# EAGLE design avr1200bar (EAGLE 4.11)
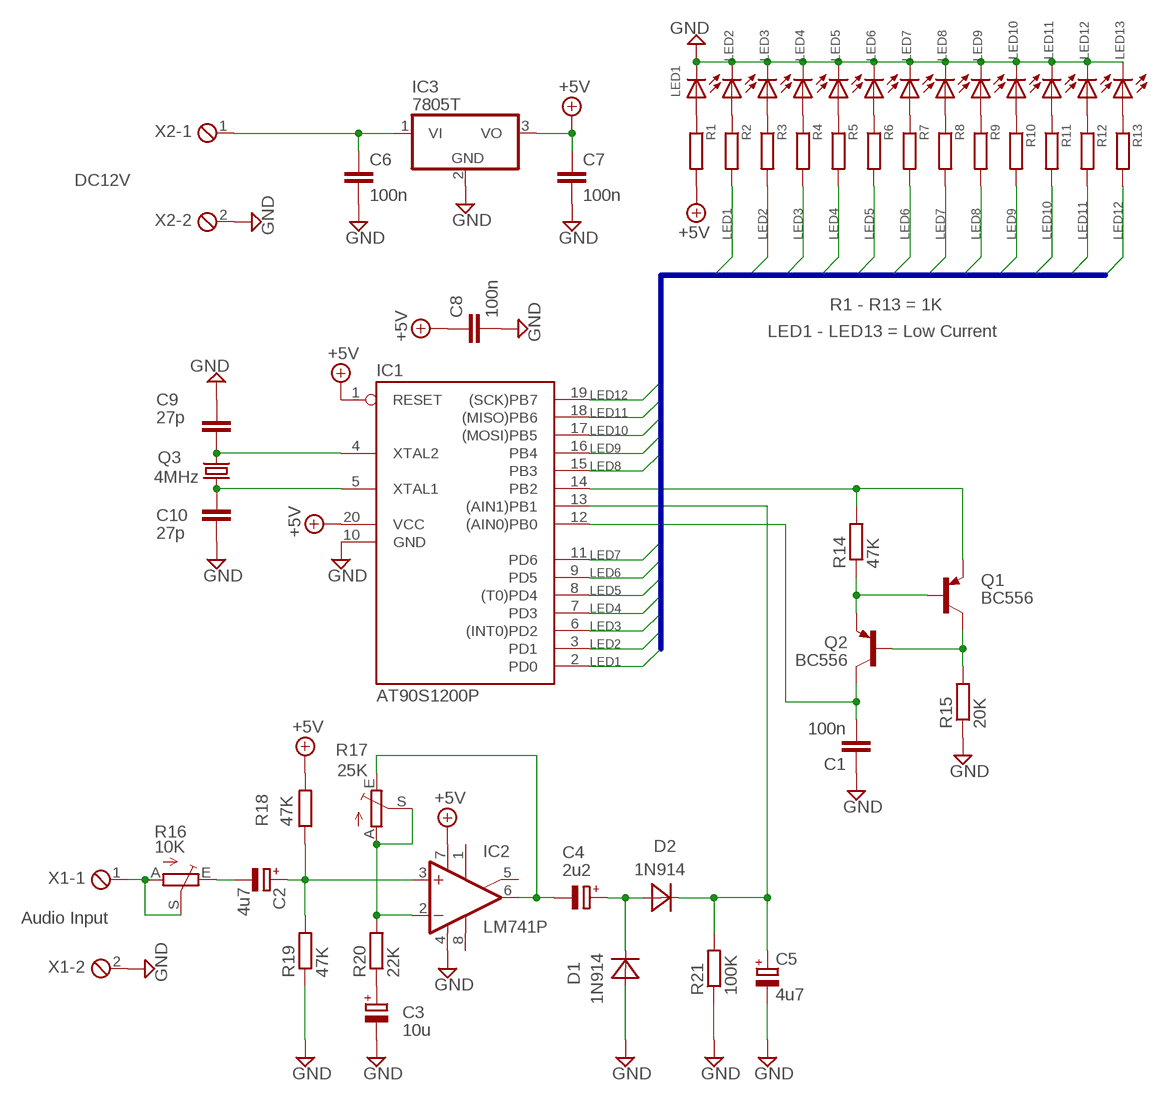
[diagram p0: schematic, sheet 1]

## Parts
C1  100n  C-EU050-025X075  [C050-025X075]
C2  4u7  CPOL-EUE2-5  [E2-5]
C3  10u  CPOL-EUE2-5  [E2-5]
C4  2u2  CPOL-EUE2-5  [E2-5]
C5  4u7  CPOL-EUE2-5  [E2-5]
C6  100n  C-EU050-025X075  [C050-025X075]
C7  100n  C-EU050-025X075  [C050-025X075]
C8  100n  C-EU050-025X075  [C050-025X075]
C9  27p  C-EU050-024X044  [C050-024X044]
C10  27p  C-EU050-024X044  [C050-024X044]
D1  1N914  DIODE-7,5  [D-7,5]
D2  1N914  DIODE-7,5  [D-7,5]
IC1  AT90S1200P  [DIL20]
IC2  LM741P  [DIL08]
IC3  7805T  7812T  [TO220H]
LED1  LEDSQR2X5  [LED2X5]
LED2  LEDSQR2X5  [LED2X5]
LED3  LEDSQR2X5  [LED2X5]
LED4  LEDSQR2X5  [LED2X5]
LED5  LEDSQR2X5  [LED2X5]
LED6  LEDSQR2X5  [LED2X5]
LED7  LEDSQR2X5  [LED2X5]
LED8  LEDSQR2X5  [LED2X5]
LED9  LEDSQR2X5  [LED2X5]
LED10  LEDSQR2X5  [LED2X5]
LED11  LEDSQR2X5  [LED2X5]
LED12  LEDSQR2X5  [LED2X5]
LED13  LEDSQR2X5  [LED2X5]
Q1  BC556  [TO92-EBC]
Q2  BC556  [TO92-EBC]
Q3  4MHz  CRYTALHC49S  [HC49/S]
R1  R-EU_0204/7  [0204/7]
R2  R-EU_0204/7  [0204/7]
R3  R-EU_0204/7  [0204/7]
R4  R-EU_0204/7  [0204/7]
R5  R-EU_0204/7  [0204/7]
R6  R-EU_0204/7  [0204/7]
R7  R-EU_0204/7  [0204/7]
R8  R-EU_0204/7  [0204/7]
R9  R-EU_0204/7  [0204/7]
R10  R-EU_0204/7  [0204/7]
R11  R-EU_0204/7  [0204/7]
R12  R-EU_0204/7  [0204/7]
R13  R-EU_0204/7  [0204/7]
R14  47K  R-EU_0204/7  [0204/7]
R15  20K  R-EU_0204/7  [0204/7]
R16  10K  TRIM_EU-CA9V  [CA9V]
R17  25K  TRIM_EU-CA9V  [CA9V]
R18  47K  R-EU_0204/7  [0204/7]
R19  47K  R-EU_0204/7  [0204/7]
R20  22K  R-EU_0204/7  [0204/7]
R21  100K  R-EU_0204/7  [0204/7]
X1  MPT2  [2POL254]
X2  MPT2  [2POL254]

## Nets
+5V: C7.1 C8.1 IC1.1(RESET) IC1.20(VCC) IC2.7(V+) IC3.3(VO) R1.2 R18.2
GND: C1.1 C3.- C5.- C6.2 C7.2 C8.2 C9.1 C10.2 D1.1(A) IC1.10(GND) IC2.4(V-) IC3.2(GND) LED1.K(C) LED2.K(C) LED3.K(C) LED4.K(C) LED5.K(C) LED6.K(C) LED7.K(C) LED8.K(C) LED9.K(C) LED10.K(C) LED11.K(C) LED12.K(C) LED13.K(C) R15.1 R19.1 R21.1 X1.2 X2.2
LED1: IC1.2(PD0) R2.2
LED2: IC1.3(PD1) R3.2
LED3: IC1.6((INT0)PD2) R4.2
LED4: IC1.7(PD3) R5.2
LED5: IC1.8((T0)PD4) R6.2
LED6: IC1.9(PD5) R7.2
LED7: IC1.11(PD6) R8.2
LED8: IC1.15(PB3) R9.2
LED9: IC1.16(PB4) R10.2
LED10: IC1.17((MOSI)PB5) R11.2
LED11: IC1.18((MISO)PB6) R12.2
LED12: IC1.19((SCK)PB7) R13.2
N$1: LED1.A R1.1
N$2: LED2.A R2.1
N$3: LED3.A R3.1
N$4: LED4.A R4.1
N$5: LED5.A R5.1
N$6: LED6.A R6.1
N$7: LED7.A R7.1
N$8: LED8.A R8.1
N$9: LED9.A R9.1
N$10: LED10.A R10.1
N$11: LED11.A R11.1
N$12: LED12.A R12.1
N$13: LED13.A R13.1
N$14: Q1.C Q2.B R15.2
N$15: C1.2 IC1.12((AIN0)PB0) Q2.C
N$16: Q1.B Q2.E R14.1
N$17: IC1.14(PB2) Q1.E R14.2
N$18: C3.+ R20.1
N$19: C2.- R16.E
N$20: C2.+ IC2.3(+IN) R18.1 R19.2
N$21: IC2.2(-IN) R17.A R17.S R20.2
N$22: C4.- IC2.6(OUT) R17.E
N$23: R16.A R16.S X1.1
N$24: C4.+ D1.2(K) D2.1(A)
N$25: C5.+ D2.2(K) IC1.13((AIN1)PB1) R21.2
N$27: C10.1 IC1.5(XTAL1) Q3.1
N$28: C9.2 IC1.4(XTAL2) Q3.2
N$29: C6.1 IC3.1(VI) X2.1
Unconnected: IC2.1(ON1) IC2.5(ON2) IC2.8(OPT)

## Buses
B$1

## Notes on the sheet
- DC12V
- R1 - R13 = 1K
- LED1 - LED13 = Low Current
- Audio Input

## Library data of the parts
C1 C6-C10 = rcl:C-EU: CAPACITOR, European symbol
C2-C5 = rcl:CPOL-EU: POLARIZED CAPACITOR, European symbol
D1 D2 = discrete:DIODE-7,5
IC1 = atmel:AT90S1200: MICROCONTROLLER 1 Kbytes FLASH 64 bytes EEPROM
IC2 = linear:*741: OP AMP
IC3 = linear:78*: Positive VOLTAGE REGULATOR
LED1-LED13 = led:LED: LED
Q1 Q2 = transistor-pnp:BC556*: PNP Transistror
Q3 = crystal:CRYTAL: CRYSTAL
R1-R15 R18-R21 = rcl:R-EU_: RESISTOR, European symbol
R16 R17 = pot:TRIM_EU-: POTENTIOMETER
X1 X2 = con-phoenix-254:MPT2: PHOENIX CONNECTOR

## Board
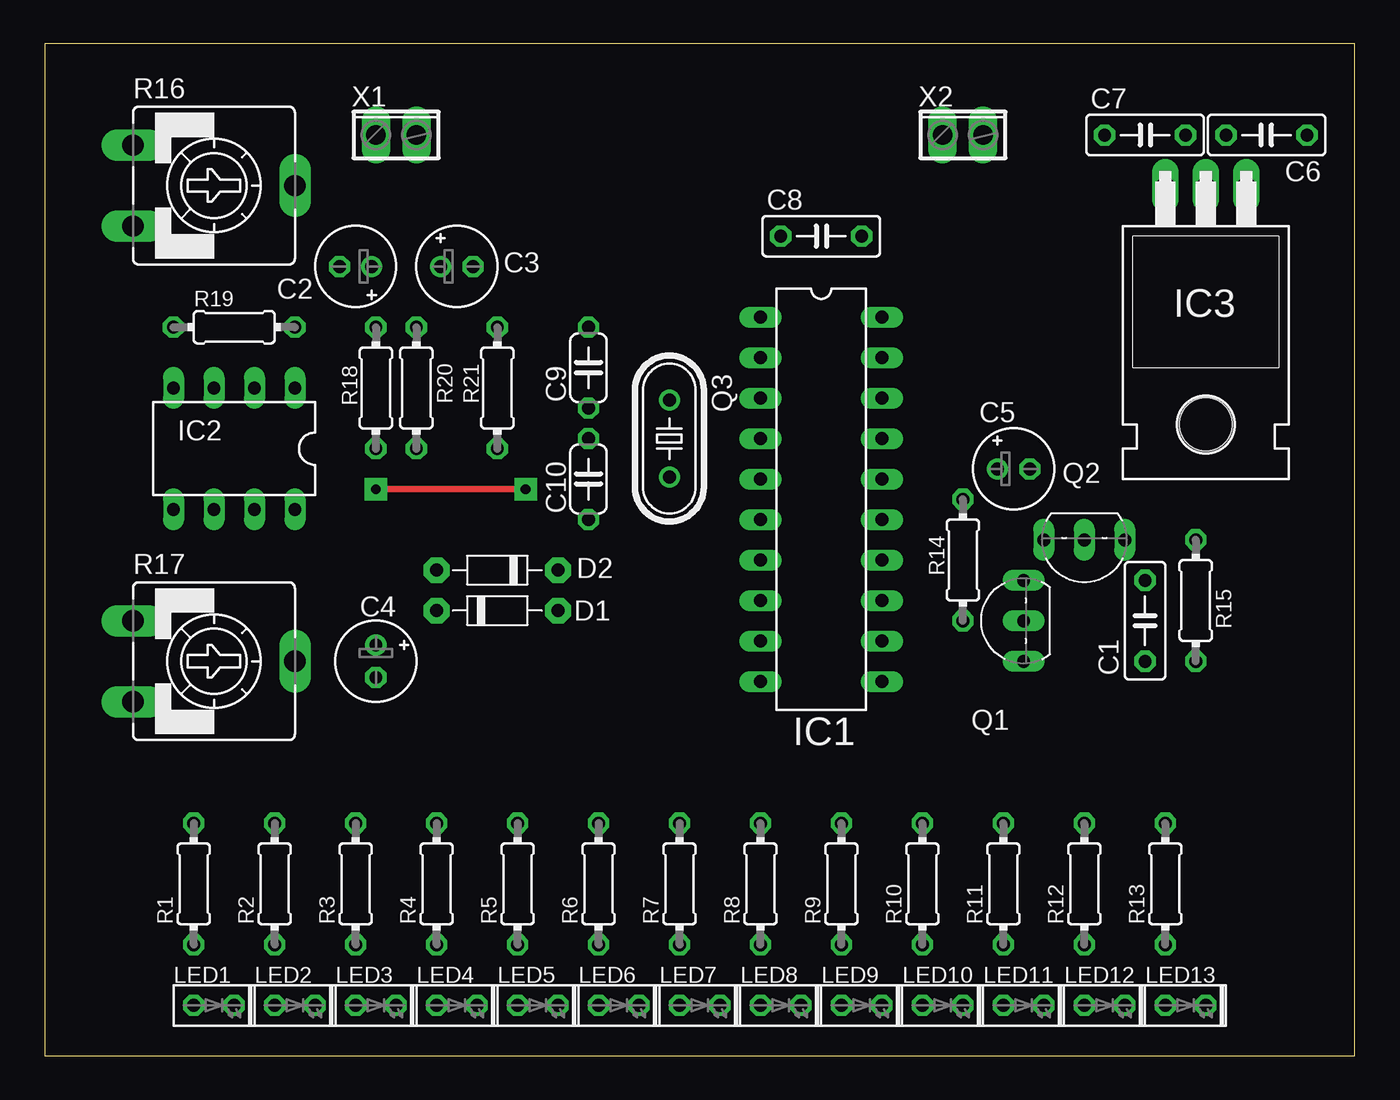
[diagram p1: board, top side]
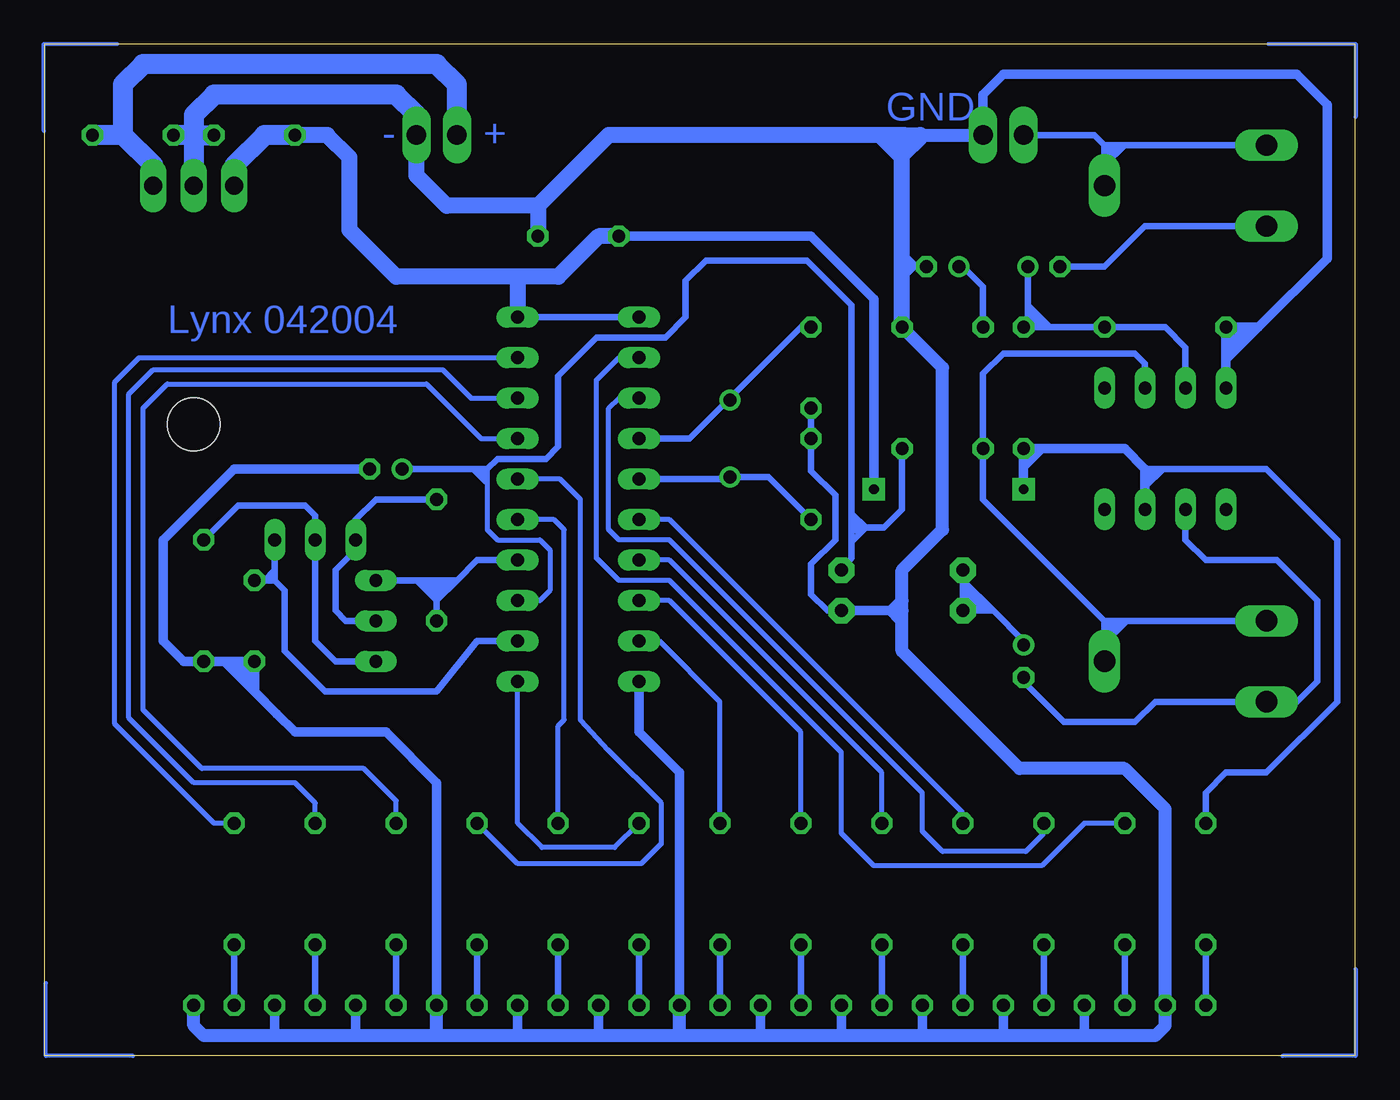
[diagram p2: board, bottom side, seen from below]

Size 82.22 x 63.49 mm. Coordinates in mm from the lower left corner, seen from the top.
Outline: 0,0 82.22,0 82.22,63.49 0,63.49 0,0
Copper layers (1*16): Top 0.035mm / dielectric 1.5mm / Bottom 0.035mm
Design rules "default": minimum track width 10mil, minimum drill 24mil, track to track 8mil, track to pad 8mil, pad to pad 8mil, via to via 8mil, smd to smd 8mil, copper to edge 40mil, drill to drill 8mil, minimum pad ring 10mil, minimum via ring 8mil, stop-mask expansion 4mil, vias tented up to drill 0mil, thermal gap 10mil

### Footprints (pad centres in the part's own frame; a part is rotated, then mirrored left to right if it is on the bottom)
C050-025X075 = drill 0.813 octagon: 1 -2.54,0; 2 2.54,0
E2-5 = drill 0.813 pad 1.27 round: + -1.016,0 | drill 0.813 pad 1.27 octagon: - 1.016,0
C050-024X044 = drill 0.813 octagon: 1 -2.54,0; 2 2.54,0
D-7,5 = drill 0.813 pad 1.6 octagon: 1 -3.81,0; 2 3.81,0
DIL20 = drill 0.813 long: 1 -11.43,-3.81; 2 -8.89,-3.81; 3 -6.35,-3.81; 4 -3.81,-3.81; 5 -1.27,-3.81; 6 1.27,-3.81; 7 3.81,-3.81; 8 6.35,-3.81; 9 8.89,-3.81; 10 11.43,-3.81; 11 11.43,3.81; 12 8.89,3.81; 13 6.35,3.81; 14 3.81,3.81; 15 1.27,3.81; 16 -1.27,3.81; 17 -3.81,3.81; 18 -6.35,3.81; 19 -8.89,3.81; 20 -11.43,3.81
DIL08 = drill 0.813 long: 1 -3.81,-3.81; 2 -1.27,-3.81; 3 1.27,-3.81; 4 3.81,-3.81; 5 3.81,3.81; 6 1.27,3.81; 7 -1.27,3.81; 8 -3.81,3.81
TO220H = drill 1.118 long: 1 -2.54,-10.16; 2 0,-10.16; 3 2.54,-10.16 | hole 3.302: 0,4.826
LED2X5 = drill 0.813 octagon: A -1.27,0; K 1.27,0
TO92-EBC = drill 0.813 long: B 0,-1.27; C -2.54,-1.27; E 2.54,-1.27
HC49/S = drill 0.813 round: 1 -2.413,0; 2 2.413,0
0204/7 = drill 0.813 octagon: 1 -3.81,0; 2 3.81,0
CA9V = drill 1.321 long: A -2.54,-5.08; E 2.54,-5.08; S 0,5.08
2POL254 = drill 1.2 long: 1 -1.27,0; 2 1.27,0

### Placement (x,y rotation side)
C1  69.05,27.3 90 top
C2  19.52,49.53 180 top
C3  25.87,49.53 0 top
C4  20.79,24.76 270 top
C5  60.8,36.83 0 top
C6  76.67,57.78 180 top
C7  69.05,57.78 0 top
C8  48.73,51.43 0 top
C9  34.12,43.18 90 top
C10  34.12,36.19 90 top
D1  28.41,27.93 180 top
D2  28.41,30.47 0 top
IC1  48.73,34.92 270 top
IC2  11.9,38.1 180 top
IC3  72.86,44.45 180 top
LED1  10.63,3.17 0 top
LED2  15.71,3.17 0 top
LED3  20.79,3.17 0 top
LED4  25.87,3.17 0 top
LED5  30.95,3.17 0 top
LED6  36.03,3.17 0 top
LED7  41.11,3.17 0 top
LED8  46.19,3.17 0 top
LED9  51.27,3.17 0 top
LED10  56.35,3.17 0 top
LED11  61.43,3.17 0 top
LED12  66.51,3.17 0 top
LED13  71.59,3.17 0 top
Q1  60.16,27.3 90 top
Q2  65.24,31.11 180 top
Q3  39.2,38.73 90 top
R1  9.36,10.79 90 top
R2  14.44,10.79 90 top
R3  19.52,10.79 90 top
R4  24.6,10.79 90 top
R5  29.68,10.79 90 top
R6  34.76,10.79 90 top
R7  39.84,10.79 90 top
R8  44.92,10.79 90 top
R9  50,10.79 90 top
R10  55.08,10.79 90 top
R11  60.16,10.79 90 top
R12  65.24,10.79 90 top
R13  70.32,10.79 90 top
R14  57.62,31.11 270 top
R15  72.22,28.57 90 top
R16  10.63,54.61 270 top
R17  10.63,24.76 270 top
R18  20.79,41.91 270 top
R19  11.9,45.72 0 top
R20  23.33,41.91 270 top
R21  28.41,41.91 270 top
X1  22.06,57.78 0 top
X2  57.62,57.78 0 top

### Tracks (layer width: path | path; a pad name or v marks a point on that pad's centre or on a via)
+5V  (via drill 0.61 pad 1.42)
  Top 0.406: v20.79,35.55 v30.19,35.55
  Bottom 0.406: R1.2 9.36,16.5 8.09,17.77 5.55,17.77 1.1,22.22 1.1,32.38 5.55,36.83 12.03,36.83 | 12.03,36.83 12.28,36.83 | 12.28,36.83 13.17,36.83 | IC1.20 IC1.1 | 12.28,36.83 12.41,36.83 13.04,36.19 | 12.03,36.83 13.17,35.68
  Bottom 0.61: IC2.7 13.17,35.68 13.17,36.83 14.44,38.1 19.65,38.1 | 19.65,38.1 R18.2 20.79,36.95 | C8.1 34.12,51.43 30.19,47.49 v30.19,35.55 | 20.79,36.95 v20.79,35.55 | 19.65,38.1 20.79,36.95
  Bottom 1.016: C7.1 64.48,57.78 63.08,56.38 63.08,51.81 60.16,48.89 52.54,48.89 | C8.1 47.46,51.43 50,48.89 52.54,48.89 | 52.54,48.89 IC1.20
  Bottom 1.27: C7.1 68.41,57.78 70.32,55.88 IC3.3
GND
  Bottom 0.406: 28.41,27.93 29.17,27.93 | 28.41,49.53 27.52,49.53 | 27.52,49.53 C3.- | C10.2 C9.1 C10.2 | 28.41,28.57 28.54,28.57 | 28.16,50.03 28.03,50.03 27.52,49.53 | 27.52,49.53 27.65,49.53 28.16,49.02 | C10.2 34.12,36.7 32.6,35.17 32.6,32.38 34.12,30.86 34.12,28.95 33.11,27.93 D1.1 | 7.07,45.72 6.69,45.59 7.96,44.32
  Bottom 0.61: 67.78,1.27 LED12.K | 62.7,1.27 LED11.K | 52.54,1.27 LED9.K | 47.46,1.27 LED8.K | 37.3,1.27 LED6.K | 32.22,1.27 LED5.K | 27.14,1.27 LED4.K | 22.06,1.27 LED3.K | 16.98,1.27 LED2.K | IC1.10 44.92,20.31 42.38,17.77 LED7.K | 70.83,24.76 C1.1 69.05,22.86 | 70.83,24.76 70.95,24.76 | 70.95,24.76 R15.1 73.5,24.76 74.77,26.03 74.77,32.38 70.32,36.83 C5.- | 67.65,21.46 66.51,20.31 60.8,20.31 57.62,17.14 LED10.K | 67.65,21.46 69.05,22.86 | 8.09,44.7 R19.1 7.07,45.72 | 8.09,44.7 8.09,43.68 | 8.09,43.68 IC2.4 | 6.06,45.72 7.07,45.72 | 6.06,45.72 1.74,50.03 1.74,59.69 3.64,61.59 22.06,61.59 23.33,60.32 X1.2 | 28.41,57.78 28.28,57.78 | 29.17,27.93 D1.1 | 29.17,27.93 28.54,28.57 | 29.17,27.93 28.54,27.3 | 7.07,45.72 8.09,44.7 | 69.05,22.86 69.05,22.98 70.83,24.76 | 70.83,24.76 70.32,24.76 69.43,23.87 | 67.65,21.46 70.95,24.76 | 6.06,45.72 8.09,43.68
  Bottom 0.813: 42.38,1.27 37.3,1.27 32.22,1.27 27.14,1.27 22.06,1.27 16.98,1.27 12.54,1.27 11.9,1.9 LED1.K 11.9,15.49 14.44,18.03 21.04,18.03 28.41,25.39 28.41,27.93 28.41,28.57 28.41,30.47 25.87,33.02 25.87,43.18 R21.1 | 42.38,1.27 47.46,1.27 52.54,1.27 57.62,1.27 | 57.62,1.27 62.7,1.27 67.78,1.27 72.22,1.27 72.86,1.9 LED13.K | 57.62,1.27 LED10.K | 42.38,1.27 LED7.K | 27.27,57.78 X1.2
  Bottom 1.016: R21.1 28.41,49.53 28.41,57.78 46.82,57.78 51.27,53.34 | 51.27,53.34 56.98,53.34 58.89,55.24 X2.2 | 51.27,53.34 C8.2 | 29.68,57.65 28.54,56.51 28.41,56.51 27.27,57.65 27.27,57.78 28.28,57.78
  Bottom 1.27: 72.86,57.78 IC3.2 | 72.86,57.78 C7.2 | 72.86,57.78 C6.2 | X2.2 58.89,59.05 60.16,60.32 71.59,60.32 72.86,59.05 72.86,57.78
LED1
  Bottom 0.305: R2.2 16.98,14.6 19.65,11.93 30.19,11.93 32.22,13.97 32.22,19.04 43.02,29.84 46.19,29.84 47.59,31.24 47.59,42.41 46.19,43.81 IC1.2
LED2
  Bottom 0.305: R3.2 19.52,13.97 20.66,12.82 25.87,12.82 27.14,14.09 27.14,16.5 43.02,32.38 46.19,32.38 46.82,33.02 46.82,40.64 46.19,41.27 IC1.3
LED3
  Bottom 0.305: R4.2 24.6,15.24 43.02,33.65 IC1.6
LED4
  Bottom 0.305: R5.2 29.68,17.77 43.02,31.11 IC1.7
LED5
  Bottom 0.305: R6.2 34.76,20.31 43.02,28.57 IC1.8
LED6
  Bottom 0.305: R7.2 39.84,22.22 43.65,26.03 IC1.9
LED7
  Bottom 0.305: R8.2 46.44,13.08 51.02,13.08 52.54,14.6 IC1.11
LED8
  Bottom 0.305: R9.2 50,20.7 49.62,21.08 49.62,33.02 50.25,33.65 IC1.15
LED9
  Bottom 0.305: R10.2 52.54,12.06 44.79,12.06 43.52,13.33 43.52,15.87 46.82,19.17 48.6,21.08 48.6,34.92 49.87,36.19 IC1.16
LED10
  Bottom 0.305: R11.2 60.16,16 62.19,18.03 72.35,18.03 76.03,21.71 76.03,40.64 74.51,42.16 58.25,42.16 54.83,38.73 IC1.17
LED11
  Bottom 0.305: R12.2 65.24,15.87 66.51,17.14 72.86,17.14 76.92,21.2 76.92,41.52 75.4,43.05 57.24,43.05 55.46,41.27 IC1.18
LED12
  Bottom 0.305: R13.2 71.59,14.6 77.81,20.82 77.81,42.29 76.29,43.81 IC1.19
N$1
  Bottom 0.406: LED1.A R1.1
N$2
  Bottom 0.406: LED2.A R2.1
N$3
  Bottom 0.406: LED3.A R3.1
N$4
  Bottom 0.406: LED4.A R4.1
N$5
  Bottom 0.406: LED5.A R5.1
N$6
  Bottom 0.406: LED6.A R6.1
N$7
  Bottom 0.406: LED7.A R7.1
N$8
  Bottom 0.406: LED8.A R8.1
N$9
  Bottom 0.406: LED9.A R9.1
N$10
  Bottom 0.406: LED10.A R10.1
N$11
  Bottom 0.406: LED11.A R11.1
N$12
  Bottom 0.406: LED12.A R12.1
N$13
  Bottom 0.406: LED13.A R13.1
N$14
  Bottom 0.406: Q1.C 63.97,24.76 65.24,26.03 Q2.B 65.24,33.9 65.88,34.54 70.07,34.54 R15.2
N$15
  Bottom 0.406: 67.78,29.84 67.78,30.6 | 67.78,30.6 Q2.C | IC1.12 55.08,26.03 57.62,22.86 64.61,22.86 67.14,25.39 67.14,29.2 67.78,29.84 | 67.78,29.84 68.41,29.84 | 68.41,29.84 C1.2 | 67.78,30.6 67.78,30.47 68.41,29.84
N$16
  Bottom 0.406: Q1.B 63.34,27.3 63.97,27.93 63.97,30.47 62.7,31.74 Q2.E 62.7,33.65 61.43,34.92 R14.1
N$17
  Bottom 0.406: 58.89,29.84 Q1.E | 57.62,28.57 58.89,29.84 | 57.62,28.57 R14.2 | IC1.14 55.08,31.11 56.35,29.84 | 56.35,29.84 57.62,28.57 | 56.35,29.84 58.89,29.84 | 56.35,29.84 56.73,29.84 57.62,28.95 57.75,28.95 58.38,29.59 57.49,29.59 | 57.49,29.59 57.24,29.59 | 57.49,29.59 57.87,29.2
N$18
  Bottom 0.406: C3.+ 24.6,49.53 23.33,48.26 R20.1
N$19
  Bottom 0.406: R16.E 13.17,52.07 15.71,49.53 C2.-
N$20
  Bottom 0.406: IC2.3 10.63,44.45 11.9,45.72 R19.2 19.14,45.72 | 19.14,45.72 19.39,45.72 | 19.39,45.72 19.65,45.72 | 19.65,45.72 R18.1 20.54,45.97 20.54,46.6 | 20.54,46.6 C2.+ | 19.65,45.72 20.54,46.6 | 19.39,45.72 19.39,45.97 | 19.39,45.97 20.41,46.98 | 19.39,45.97 19.14,45.72
N$21
  Bottom 0.406: IC2.2 13.17,43.43 13.81,44.06 22.06,44.06 23.33,42.79 R20.2 23.33,34.92 15.71,27.3 | R17.A 14.31,27.3 | 14.31,27.3 14.82,27.3 | 14.82,27.3 15.71,27.3 | 15.71,26.79 15.71,25.9 | 15.71,25.9 R17.S | 15.71,27.3 15.71,26.79 | 14.82,27.3 15.2,27.3 15.71,26.79 | 14.31,27.3 14.69,27.3 15.58,26.41 | 14.44,27.17 15.71,25.9
N$22
  Bottom 0.406: C4.- 20.79,23.49 18.25,20.95 13.81,20.95 12.54,22.22 R17.E 3.64,22.22 2.38,23.49 2.38,28.57 4.92,31.11 9.36,31.11 10.63,32.38 IC2.6
N$23
  Bottom 0.406: X1.1 16.34,57.78 15.71,57.15 | 15.71,56.51 15.71,57.15 | 15.71,56.13 15.71,56.51 | 15.71,56.13 15.71,55.88 | 15.71,55.88 R16.S | R16.A 14.44,57.15 | 14.44,57.15 14.69,57.15 | 14.69,57.15 15.08,57.15 | 15.08,57.15 15.71,57.15 | 15.08,57.15 15.71,56.51 | 14.69,57.15 15.71,56.13 | 14.44,57.15 15.71,55.88
N$24
  Bottom 0.406: 24.6,29.84 D1.2 22.7,27.93 | 24.6,29.84 D2.1 | C4.+ 20.79,26.03 22.7,27.93 | 22.7,27.93 24.6,29.84 | 24.6,29.84 24.6,29.46 23.33,28.19 23.71,28.19 24.47,28.95 24.47,28.57 24.09,28.19
N$25
  Bottom 0.305: IC1.13 51.14,28.57 50.51,29.2 50.51,31.74 51.14,32.38 53.81,32.38 54.45,33.02 54.45,36.83
  Bottom 0.406: C5.+ 54.45,36.83 53.81,37.46 50.76,37.46 50,38.22 50,42.67 47.59,45.08 43.27,45.08 42,46.35 42,48.64 40.73,49.91 34.38,49.91 31.58,47.11 31.58,34.03 | R21.2 28.41,34.29 29.55,33.14 30.7,33.14 | D2.2 32.22,30.35 31.58,31.24 31.58,32.25 | 31.58,32.25 31.58,33.14 | 31.58,33.14 31.58,34.03 | 31.58,33.14 30.7,33.14 | 31.58,32.25 30.7,33.14 | 30.7,33.14 31.58,34.03 | 31.58,34.03 31.58,33.78 31.2,33.4 31.2,32.89
N$26
  Bottom 0.406: 54.83,36.7 54.57,36.44
N$27
  Bottom 0.406: IC1.5 39.46,36.19 Q3.1 36.79,36.32 C10.1
N$28
  Bottom 0.406: IC1.4 41.74,38.73 39.2,41.27 | 39.2,41.27 Q3.2 | C9.2 34.76,45.72 39.2,41.27
N$29
  Bottom 0.61: 75.4,55.88 75.4,55.75 75.53,55.62 75.4,55.49 IC3.1
  Bottom 1.27: 77.3,57.78 C6.1 | 77.3,57.78 75.4,55.88 | X2.1 56.35,60.96 57.62,62.23 76.03,62.23 77.3,60.96 77.3,57.78
N$30
  Bottom 0.406: 54.57,36.06 55.21,36.7
N$32
  Bottom 0.254: -0.04,5.46 -0.04,-0.01 4.53,-0.01
N$33
  Bottom 0.254: 5.42,63.5 -0.04,63.5 -0.04,58.92
N$34
  Bottom 0.254: 82.26,58.03 82.26,63.5 77.69,63.5
N$35
  Bottom 0.254: 76.67,-0.01 82.13,-0.01 82.13,4.57

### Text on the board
Bottom: GND | + | - | Lynx 042004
